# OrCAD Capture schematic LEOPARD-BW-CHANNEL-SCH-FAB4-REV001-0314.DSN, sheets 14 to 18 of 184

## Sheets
14 165_PVTT_GH_MOSFET: size A3; title: PVTT_GH_MOSFET
15 164_PVDDQ_GH_MOSFET: size C; title: PVDDQ_GH_MOSFET
16 163_PVDDQ_GH_Controller: size C; title: PVDDQ_GH_CONTROLLER
17 162_PVPP_EF_TPS53318: size A3; title: PVPP_EF_TPS53318
18 161_PVDDQ_EF_Decoupling: size A3; title: PVDDQ_EF_DECOUPLING

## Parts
sheet 161_PVDDQ_EF_Decoupling
PC545  SCD1U25V5KX-1GP  [C805H54]
PC546  SC1U25V6KX-2GP  [C1206H45]
PC547  SCD1U25V5KX-1GP  [C805H54]
PC548  SE470UF2VDM-GP  [CT7343H83]
PC549  SE470UF2VDM-GP  [CT7343H83]
PC550  SE470UF2VDM-GP  [CT7343H83]
PC551  SE470UF2VDM-GP  [CT7343H83]
PC552  SC47U4V5MX-2-GP  [C805H58]
PC553  SC47U4V5MX-2-GP  [C805H58]
PC554  SC47U4V5MX-2-GP  [C805H58]
PC555  SC47U4V5MX-2-GP  [C805H58]
PC556  SC22U6D3V5MX-5-GP  [C805H56]
PC557  SC22U6D3V5MX-5-GP  [C805H56]
PC558  SC22U6D3V5MX-5-GP  [C805H56]
PC559  SC22U6D3V5MX-5-GP  [C805H56]
PC560  SC22U6D3V5MX-5-GP  [C805H56]
PC561  SC22U6D3V5MX-5-GP  [C805H56]
PC562  SC22U6D3V5MX-5-GP  [C805H56]
PC563  SC22U6D3V5MX-5-GP  [C805H56]
PC564  SC22U6D3V5MX-5-GP  [C805H56]
PC565  SC22U6D3V5MX-5-GP  [C805H56]
PC566  SC22U6D3V5MX-5-GP  [C805H56]
PC567  SC22U6D3V5MX-5-GP  [C805H56]
PC568  SC22U6D3V5MX-5-GP  [C805H56]
PC569  SC22U6D3V5MX-5-GP  [C805H56]
PC570  SC22U6D3V5MX-5-GP  [C805H56]
PC571  SC22U6D3V5MX-5-GP  [C805H56]
PC572  SC22U6D3V5MX-5-GP  [C805H56]
PC573  SC22U6D3V5MX-5-GP  [C805H56]
PC574  SC22U6D3V5MX-5-GP  [C805H56]
PC575  SC22U6D3V5MX-5-GP  [C805H56]
PC576  SC22U6D3V5MX-5-GP  [C805H56]
PC577  SC22U6D3V5MX-5-GP  [C805H56]
PC578  SC22U6D3V5MX-5-GP  [C805H56]
PC579  SC22U6D3V5MX-5-GP  [C805H56]
PC580  SC22U6D3V5MX-5-GP  [C805H56]
PC581  SC22U6D3V5MX-5-GP  [C805H56]
PC582  SC22U6D3V5MX-5-GP  [C805H56]
PC583  SC22U6D3V5MX-5-GP  [C805H56]
PC584  SC22U6D3V5MX-5-GP  [C805H56]
PC585  SC22U6D3V5MX-5-GP  [C805H56]
PC586  SC22U6D3V5MX-5-GP  [C805H56]
PC587  SC22U6D3V5MX-5-GP  [C805H56]
PC588  SC22U6D3V5MX-5-GP  [C805H56]
PC589  SC22U6D3V5MX-5-GP  [C805H56]
PC590  SC22U6D3V5MX-5-GP  [C805H56]
PC591  SC22U6D3V5MX-5-GP  [C805H56]
PC592  SC22U6D3V5MX-5-GP  [C805H56]
PC593  SC22U6D3V5MX-5-GP  [C805H56]
PC594  SC22U6D3V5MX-5-GP  [C805H56]
PC595  SC22U6D3V5MX-5-GP  [C805H56]
PC857  SC22U6D3V5MX-5-GP  [C805H56]
PC858  SC22U6D3V5MX-5-GP  [C805H56]
PC859  SC22U6D3V5MX-5-GP  [C805H56]
PC860  SC22U6D3V5MX-5-GP  [C805H56]
PC861  SC22U6D3V5MX-5-GP  [C805H56]
PC862  SC22U6D3V5MX-5-GP  [C805H56]
PC863  SC22U6D3V5MX-5-GP  [C805H56]
PC864  SC22U6D3V5MX-5-GP  [C805H56]
PC1000  SC22U6D3V5MX-5-GP  [C805H56]
PC1001  SC22U6D3V5MX-5-GP  [C805H56]
PC1002  SC22U6D3V5MX-5-GP  [C805H56]
PL44  IND-65NH-GP  [L4038-1412H158]
PR329  33R3F-L-GP  [R603H22]
PR330  0R2F-L-GP  [R402H16]
PR331  0R2F-L-GP  [R402H16]
PTC7  E270U16VM-28-GP  [ECAP-100D6D3H363]
sheet 162_PVPP_EF_TPS53318
PC596  SC10U16V5KX-1-GP  [C805H54]
PC597  SC10U16V5KX-1-GP  [C805H54]
PC598  SC10U16V5KX-1-GP  [C805H54]
PC599  SC10U16V5KX-1-GP  [C805H54]
PC600  SCD1U16V3KX-3GP  [C603H36]
PC601  SC4D7U25V5KX-1-GP  [C805H58]
PC602  SCD1U50V3KX-GP  [C603H36]
PC603  SC2K2P50V3KX-GP  [C603]
PC604  SC1U10V2KX-4-GP  [C402H22]
PC605  SCD1U16V2KX-3GP  [C402H22]
PC606  SC1KP50V2KX-1GP  [C402H22]
PC607  SCD1U16V3KX-3GP  [C603H36]
PC608  SC22U6D3V5MX-5-GP  [C805H56]
PC609  SC47U4V5MX-2-GP  [C805H58]
PC610  SC47U4V5MX-2-GP  [C805H58]
PC611  SC47U4V5MX-2-GP  [C805H58]
PC612  SC47U4V5MX-2-GP  [C805H58]
PC613  SC47U4V5MX-2-GP  [C805H58]
PC614  SC47U4V5MX-2-GP  [C805H58]
PC1043  SC1U10V2KX-4-GP  [C402H22]
PD24  BZT52-C3V3S-GP  [SOD323AKH38]
PL29  BLM21PG220SN1DGP  [L20125H42]
PL30  IND-2D2UH-242-GP  [L7165-1732H119]
PR332  2D2R3-1-U-GP  [R603H22]
PR333  3D01R5F-GP  [R805H24]
PR335  0R2J-2-GP  [R402H16]
PR336  3K9R2F-GP  [R402H16]
PR337  10R3F-GP  [R603H22]
PR338  100KR2F-L1-GP  [R402H16]
PR339  3D01R5F-GP  [R805H24]
PR340  100KR2F-L1-GP  [R402H16]
PR341  100KR2F-L1-GP  [R402H16]
PR342  866KR2F-GP  [R402H16]
PR343  619KR2F-GP  [R402H16]
PR344  31K6R2F-GP  [R402H16]
PR345  10KR2F-2-GP  [R402H16]
PR346  0R3J-0-U-GP  [R603H22]
PR645  10KR2F-2-GP  [R402H16]
PR802  0R2J-2-GP  [R402H16]
PU30  TPS53318DQPR-GP  [DFN22G6050-G6133H60]
sheet 163_PVDDQ_GH_Controller
PC1469  SC220P50V2JN-3GP  [C402H22]
PC1487  SC1KP50V2KX-1GP  [C402H22]
PC1488  SC1U10V2KX-4-GP  [C402H22]
PC1489  SCD1U16V2KX-3GP  [C402H22]
PC1490  SC1U10V2KX-4-GP  [C402H22]
PC1491  SCD1U16V2KX-3GP  [C402H22]
PC1495  SC220P50V2KX-3GP  [C402H22]
PC1496  SCD47U25V3KX-3-GP  [C603H36]
PC1497  SC10U4V3MX-3-GP  [C603H40]
PC1498  SCD1U16V2KX-3GP  [C402H22]
PC1499  SC220P50V2KX-3GP  [C402H22]
PC1500  SC220P50V2JN-3GP  [C402H22]
PC1623  SC220P50V2JN-3GP  [C402H22]
PC7337  SCD47U6D3V2KX-1-GP  [C402H22]
PC7338  SCD47U6D3V2KX-1-GP  [C402H22]
PQ14  NST3906F3T5G-GP-U  [SOT-1123CBE1006-1H16]
PR1941  0R2J-2-GP  [R402H16]
PR2122  19K1R2F-GP  [R402H16]
PR2123  1KR2F-3-GP  [R402H16]
PR2124  0R2J-2-GP  [R402H16]
PR2128  1KR2F-3-GP  [R402H16]
PR2130  1KR2F-3-GP  [R402H16]
PR2131  0R2J-2-GP  [R402H16]
PR2132  0R2J-2-GP  [R402H16]
PR2133  10R3F-GP  [R603H22]
PR2135  0R2J-2-GP  [R402H16]
PR2136  0R0402-PAD-1-GP  [0R0402-PAD]
PR2139  16KR2F-GP  [R402H16]
PR2140  3K16R2F-GP  [R402H16]
PR2141  549R2F-GP  [R402H16]
PR2142  8K06R2F-GP  [R402H16]
PR2143  10R3F-GP  [R603H22]
PR2144  100R2F-L1-GP-U  [R402H14]
PR2145  0R2J-2-GP  [R402H16]
PR2146  100R2F-L1-GP-U  [R402H14]
PR2147  49D9R2F-GP  [R402H16]
PR2148  0R0402-PAD-1-GP  [0R0402-PAD]
PR2149  0R2J-2-GP  [R402H16]
PR2150  0R2J-2-GP  [R402H16]
PR2151  150R2F-1-GP  [R402H16]
PTP6  TP20B24R10-B-GP  [TP20B24R10-B]
PU31  PX3244HDM-1-GP  [QFN40J5-G3D75H36]
sheet 164_PVDDQ_GH_MOSFET
PC1566  SCD47U25V3KX-3-GP  [C603H36]
PC1567  SC10U16V5KX-1-GP  [C805H54]
PC1568  SC10U16V5KX-1-GP  [C805H54]
PC1569  SC10U16V5KX-1-GP  [C805H54]
PC1570  SCD1U16V2KX-3GP  [C402H22]
PC1571  SC1U25V3KX-GP  [C603H36]
PC1572  SCD1U16V2KX-3GP  [C402H22]
PC1573  SC1U10V2KX-4-GP  [C402H22]
PC1574  SCD22U16V2KX-GP  [C402H22]
PC1575  SC1U10V2KX-4-GP  [C402H22]
PC1576  SCD47U25V3KX-3-GP  [C603H36]
PC1577  SC10U16V5KX-1-GP  [C805H54]
PC1578  SC10U16V5KX-1-GP  [C805H54]
PC1579  SCD1U16V2KX-3GP  [C402H22]
PC1580  SC10U16V5KX-1-GP  [C805H54]
PC1581  SC1U25V3KX-GP  [C603H36]
PC1582  SCD1U16V2KX-3GP  [C402H22]
PC1583  SC1U10V2KX-4-GP  [C402H22]
PC1584  SCD22U16V2KX-GP  [C402H22]
PC1585  SC1U10V2KX-4-GP  [C402H22]
PG75  COPPER-CLOSE-GP-U  [CON2C-U]
PG76  COPPER-CLOSE-GP-U  [CON2C-U]
PG77  COPPER-CLOSE-GP-U  [CON2C-U]
PG78  COPPER-CLOSE-GP-U  [CON2C-U]
PL89  IND-150NH-15-GP  [L102078-254224H296]
PL96  IND-150NH-15-GP  [L102078-254224H296]
PR40  0R2J-2-GP  [R402H16]
PR41  0R2J-2-GP  [R402H16]
PR58  0R2J-2-GP  [R402H16]
PR59  0R2J-2-GP  [R402H16]
PR2217  1R2F-GP  [R402H16]
PR2254  1R2F-GP  [R402H16]
PR2255  10KR2F-2-GP  [R402H16]
PR2256  10KR2F-2-GP  [R402H16]
PR2275  0R3J-6-GP  [R603H22]
PR2277  0R3J-6-GP  [R603H22]
PR6655  562R2F-GP  [R402H16]
PR6656  562R2F-GP  [R402H16]
PR6669  562R2F-GP  [R402H16]
PR6670  562R2F-GP  [R402H16]
PTP35  TPAD24  [TPAD24]
PTP36  TPAD24  [TPAD24]
PTP49  TPAD24  [TPAD24]
PTP50  TPAD24  [TPAD24]
PU192  TDA21232-GP  [QFN31G5-G4P-7H38]
PU199  TDA21232-GP  [QFN31G5-G4P-7H38]
sheet 165_PVTT_GH_MOSFET
PC648  SC1U10V2KX-4-GP  [C402H22]
PC649  SCD22U16V2KX-GP  [C402H22]
PC651  SCD22U16V2KX-GP  [C402H22]
PC653  SC1U25V3KX-GP  [C603H36]
PC656  SC10U16V5KX-1-GP  [C805H54]
PC657  SC10U16V5KX-1-GP  [C805H54]
PC658  SCD47U25V3KX-3-GP  [C603H36]
PC659  SC220P50V2JN-3GP  [C402H22]
PC660  SC47U4V5MX-2-GP  [C805H58]
PC661  SC47U4V5MX-2-GP  [C805H58]
PC662  SC22U6D3V5MX-5-GP  [C805H56]
PC663  SC22U6D3V5MX-5-GP  [C805H56]
PC664  SC22U6D3V5MX-5-GP  [C805H56]
PC665  SC22U6D3V5MX-5-GP  [C805H56]
PC666  SC22U6D3V5MX-5-GP  [C805H56]
PC667  SC22U6D3V5MX-5-GP  [C805H56]
PC668  SC22U6D3V5MX-5-GP  [C805H56]
PC669  SC22U6D3V5MX-5-GP  [C805H56]
PC670  SC22U6D3V5MX-5-GP  [C805H56]
PC671  SC22U6D3V5MX-5-GP  [C805H56]
PC672  SC22U6D3V5MX-5-GP  [C805H56]
PC673  SC22U6D3V5MX-5-GP  [C805H56]
PC674  SE470UF2VDM-GP  [CT7343H83]
PG43  COPPER-CLOSE-GP-U  [CON2C-U]
PG44  COPPER-CLOSE-GP-U  [CON2C-U]
PL33  IND-1UH-101-GP  [L6868-3612H166]
PQ10  NST3906F3T5G-GP-U  [SOT-1123CBE1006-1H16]
PR392  2D2R2F-GP  [R402H16]
PR394  10KR2F-2-GP  [R402H16]
PR395  93K1R2F-L-GP  [R402H16]
PR398  562R2F-GP  [R402H16]
PR399  562R2F-GP  [R402H16]
PR400  0R2F-L-GP  [R402H16]
PR401  0R2F-L-GP  [R402H16]
PR402  120R3F-L-GP  [R603H22]
PR858  0R3J-0-U-GP  [R603H22]
PR859  0R3J-0-U-GP  [R603H22]
PU34  PX3517-GP  [DFN10G3-G2619H36]
PU35  AON7934-GP  [MLP8F3-G2P-1H32]

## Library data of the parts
PC545 PC547 = SCD1U25V5KX-1GP: CHIP CAP0.1U25V K0805 X7R(ROHS; GREENDFACTOR: R2_SA;HF_SA;G_SA;; Package Type: SMD-BCG; Part Number: 78.10422.21L; SPEC: http://wpqssvr.wistron.com.tw:7001/wpqs/servlet/COM.qpart.Attachment?PartNumber=78.10422.21L
PC546 = SC1U25V6KX-2GP: CHIP CAP C 1U 25V K1206 X7R; GREENDFACTOR: R2_SA;HF_SA;G_SA;; Package Type: SMD-BCG1; Part Number: 78.10522.22L; SPEC: http://wpqssvr.wistron.com.tw:7001/wpqs/servlet/COM.qpart.Attachment?PartNumber=78.10522.22L
PC548-PC551 PC674 = SE470UF2VDM-GP: CHIP CAP 470UF 2V EEFSX0D471X; GREENDFACTOR: R_SA;; Module: VR_DDR_P1V5_VDDQ; Package Type: SMD-TCG1; Part Number: 79.47719.2BL; Part Type: SMD-TCG1; Part_Function: Cout_bulk; Part_Spec: 470uF/2V/6mohm; Part_Type: Solid_al_cap; SPEC: http://wpqssvr.wistron.com.tw:7001/wpqs/servlet/COM.qpart.Attachment?PartNumber=79.47719.2BL; VENDOR_PN: EEFSX0D471XE
PC552-PC555 PC609-PC614 PC660 PC661 = SC47U4V5MX-2-GP: CHIP CAP C 47U 4V M0805 X6S; GREENDFACTOR: R2_SA;HF_SA;G_SA;; Package Type: SMD-BCG3; Part Number: 78.4761T.81L; SPEC: http://wpqssvr.wistron.com.tw:7001/wpqs/servlet/COM.qpart.Attachment?PartNumber=78.4761T.81L
PC556-PC595 PC608 PC662-PC673 PC857-PC864 = SC22U6D3V5MX-5-GP: CHIP CAP C 22U 6.3V M0805 X6S; GREENDFACTOR: R2_SA;HF_SA;G_SA;; Package Type: SMD-BCG2; Part Number: 78.22610.81L; SPEC: http://wpqssvr.wistron.com.tw:7001/wpqs/servlet/COM.qpart.Attachment?PartNumber=78.22610.81L
PC1000-PC1002 = SC22U6D3V5MX-5-GP: CHIP CAP C 22U 6.3V M0805 X6S; GREENDFACTOR: R2_SA;HF_SA;G_SA;; Package Type: SMD-BCG2; Part Number: 78.22610.81L; SPEC: http://wpqssvr.wistron.com.tw:7001/wpqs/servlet/COM.qpart.Attachment?PartNumber=78.22610.81L; Size: 0805; Type: X6S
PL44 = IND-65NH-GP: CHIP IND 65NH FP0404R1-R065-R; GREENDFACTOR: R2_SA;; Part Number: 68.650CN.101; Part Type: DISCRET-G6; SPEC: http://wpqssvr.wistron.com.tw:7001/wpqs/servlet/COM.qpart.Attachment?PartNumber=68.650CN.101
PR329 = 33R3F-L-GP: CHIP RES 33 F 1/10W 0603; GREENDFACTOR: R2_SA;HF_SA;G_SA;; Package Type: SMD-RG; Part Number: 64.33R05.55L; SPEC: http://wpqssvr.wistron.com.tw:7001/wpqs/servlet/COM.qpart.Attachment?PartNumber=64.33R05.55L
PR330 PR331 PR400 PR401 = 0R2F-L-GP: CHIP RES 0 F 0402 RK73Z1ETTP KOA; GREENDFACTOR: R2_SA;; Package Type: SMD-RG5; Part Number: 64.R0005.L0L; SPEC: http://wpqssvr.wistron.com.tw:7001/wpqs/servlet/COM.qpart.Attachment?PartNumber=64.R0005.L0L
PTC7 = E270U16VM-28-GP: CAP EL 270U 16V RT2.5 6.3*8 SOLID CAP; GREENDFACTOR: R2_SA;HF_SA;; Part Number: 09.2771D.E4L; Part Spec: 270uF/16V/10mohm/5A; Part Type: DIP-TCG4; SPEC: http://wpqssvr.wistron.com.tw:7001/wpqs/servlet/COM.qpart.Attachment?PartNumber=09.2771D.E4L
PC596-PC599 PC656 PC657 PC1567-PC1569 PC1577 PC1578 PC1580 = SC10U16V5KX-1-GP: CHIP CAP C 10U 16V K0805 X6S; GREENDFACTOR: R2_SA;; Package Type: SMD-BCG5; Part Number: 78.10621.81L; SPEC: http://wpqssvr.wistron.com.tw:7001/wpqs/servlet/COM.qpart.Attachment?PartNumber=78.10621.81L
PC600 PC607 = SCD1U16V3KX-3GP: CHIP CAP 0.1U16V K0603 X7R(ROH; GREENDFACTOR: R2_SA;R_SA;HF_SA;G_SA;; Module: VR_SYSTEM_P1V8; Package Type: SMD-BCG; Part Number: 78.10421.2BL; SPEC: http://wpqssvr.wistron.com.tw:7001/wpqs/servlet/COM.qpart.Attachment?PartNumber=78.10421.2BL; Size: 0603; Type: X7R
PC601 = SC4D7U25V5KX-1-GP: CHIP CAP C 4.7U 25V K0805 X7R; GREENDFACTOR: R2_SA;HF_SA;G_SA;; Package Type: SMD-BCG4; Part Number: 078.47522.0211; SPEC: http://wpqssvr.wistron.com.tw:7001/wpqs/servlet/COM.qpart.Attachment?PartNumber=078.47522.0211
PC602 = SCD1U50V3KX-GP: CHIP CAP C 0.1U 50V K0603 X7R; GREENDFACTOR: R2_SA;HF_SA;G_SA;; Level: SMD; MAIN_SOURCE: M; Package Type: RCL_GP; Part Number: 78.10424.2BL; Part Type: RCL_GP; SPEC: http://wpqssvr.wistron.com.tw:7001/wpqs/servlet/COM.qpart.Attachment?PartNumber=78.10424.2BL; Status: POP
PC603 = SC2K2P50V3KX-GP: CHIP CAP C 2200P 50V K0603 X7R; GREENDFACTOR: R2_SA;HF_SA;G_SA;; Level: SMD; POP?: NOPOP; Package Type: SMD-BCG6; Part Number: 78.22224.2BL; Part Type: SMD-BCG6; SPEC: http://wpqssvr.wistron.com.tw:7001/wpqs/servlet/COM.qpart.Attachment?PartNumber=78.22224.2BL; Status: POP
PC604 PC648 PC1488 PC1490 PC1573 PC1575 PC1583 PC1585 = SC1U10V2KX-4-GP: CHIP CAP C 1U 10V K 0402 X6S; GREENDFACTOR: R2_SA;HF_SA;; Package Type: SMD-BCG6; Part Number: 78.10523.8FL; SPEC: http://wpqssvr.wistron.com.tw:7001/wpqs/servlet/COM.qpart.Attachment?PartNumber=78.10523.8FL
PC605 PC1498 = SCD1U16V2KX-3GP: CHIP CAP C 0.1U 16V K0402 X7R; CATEGORIES: CAP_1.xV; GREENDFACTOR: R2_SA;HF_SA;G_SA;; MAIN_SOURCE: M; Part Number: 78.10421.2FL; Part Type: SMD-BCG; SPEC: http://wpqssvr.wistron.com.tw:7001/wpqs/servlet/COM.qpart.Attachment?PartNumber=78.10421.2FL
PC606 = SC1KP50V2KX-1GP: CHIP CAP 1000P50V K0402 X7R(RO; GREENDFACTOR: R2_SA;HF_SA;G_SA;; Level: SMD; MAIN_SOURCE: M; Package Type: SMD-BCG; Part Number: 78.10224.2FL; Part Type: SMD-BCG; SPEC: http://wpqssvr.wistron.com.tw:7001/wpqs/servlet/COM.qpart.Attachment?PartNumber=78.10224.2FL; Status: POP
PC1043 = SC1U10V2KX-4-GP: CHIP CAP C 1U 10V K 0402 X6S; GREENDFACTOR: R2_SA;HF_SA;; POP?: NOPOP; Package Type: SMD-BCG6; Part Number: 78.10523.8FL; SPEC: http://wpqssvr.wistron.com.tw:7001/wpqs/servlet/COM.qpart.Attachment?PartNumber=78.10523.8FL
PD24 = BZT52-C3V3S-GP: DIODE ZEN BZT52-C3V3S 3.3V SOD-323; GREENDFACTOR: R2_SA;; Part Number: 83.3R303.G3F; Part Type: DISCRET-G4; SPEC: http://wpqssvr.wistron.com.tw:7001/wpqs/servlet/COM.qpart.Attachment?PartNumber=83.3R303.G3F
PL29 = BLM21PG220SN1DGP: CHIP BEAD BLM21PG220SN1D (LF); GREENDFACTOR: R2_SA;HF_SA;; Level: SMD; Package Type: DISCRET-G; Part Number: 68.00084.831; Part Type: DISCRET-G; SPEC: http://wpqssvr.wistron.com.tw:7001/wpqs/servlet/COM.qpart.Attachment?PartNumber=68.00084.831; Status: POP
PL30 = IND-2D2UH-242-GP: CHIP IND 2.2UH M SPM6530T-2R2M; GREENDFACTOR: R2_SA;HF_SA;; Package Type: DISCRET-G6; Part Number: 68.2R21E.10X; SPEC: http://wpqssvr.wistron.com.tw:7001/wpqs/servlet/COM.qpart.Attachment?PartNumber=68.2R21E.10X
PR332 = 2D2R3-1-U-GP: CHIP RES 2.2 F 1/10W 0603(ROHS; GREENDFACTOR: R2_SA;HF_SA;G_SA;; Package Type: RCL_GP; Part Number: 64.2R205.55L; SPEC: http://wpqssvr.wistron.com.tw:7001/wpqs/servlet/COM.qpart.Attachment?PartNumber=64.2R205.55L
PR333 = 3D01R5F-GP: CHIP RES 3.01 F 1/8W 0805; GREENDFACTOR: R2_SA;HF_SA;G_SA;; Level: SMD; Package Type: SMD-RG5; Part Number: 64.3R015.16L; Part Type: SMD-RG5; SPEC: http://wpqssvr.wistron.com.tw:7001/wpqs/servlet/COM.qpart.Attachment?PartNumber=64.3R015.16L; Status: POP
PR335 PR802 = 0R2J-2-GP: CHIP RES 0 J 1/16W 0402; GREENDFACTOR: R2_SA;HF_SA;G_SA;; Level: SMD; Package Type: SMD-RG; Part Number: 63.R0034.1DL; Part Type: SMD-RG; ROOM: VR_CHIPSET; SPEC: http://wpqssvr.wistron.com.tw:7001/wpqs/servlet/COM.qpart.Attachment?PartNumber=63.R0034.1DL; Status: POP
PR336 = 3K9R2F-GP: CHIP RES 3.9K F 1/16W 0402; GREENDFACTOR: R2_SA;HF_SA;G_SA;; Package Type: RCL_GP; Part Number: 64.39015.6DL; SPEC: http://wpqssvr.wistron.com.tw:7001/wpqs/servlet/COM.qpart.Attachment?PartNumber=64.39015.6DL
PR337 PR2133 PR2143 = 10R3F-GP: CHIP RES 10 F 1/10W 0603; GREENDFACTOR: R2_SA;HF_SA;G_SA;; Level: SMD; Package Type: RCL_GP; Part Number: 64.10R05.55L; Part Type: RCL_GP; SPEC: http://wpqssvr.wistron.com.tw:7001/wpqs/servlet/COM.qpart.Attachment?PartNumber=64.10R05.55L; Status: POP
PR338 = 100KR2F-L1-GP: CHIP RES 100K F 1/16W 0402; GREENDFACTOR: R2_SA;HF_SA;G_SA;; Part Number: 64.10035.6DL; Part Type: SMD-RG; SPEC: http://wpqssvr.wistron.com.tw:7001/wpqs/servlet/COM.qpart.Attachment?PartNumber=64.10035.6DL
PR339 = 3D01R5F-GP: CHIP RES 3.01 F 1/8W 0805; GREENDFACTOR: R2_SA;HF_SA;G_SA;; Level: SMD; POP?: NOPOP; Package Type: SMD-RG5; Part Number: 64.3R015.16L; Part Type: SMD-RG5; SPEC: http://wpqssvr.wistron.com.tw:7001/wpqs/servlet/COM.qpart.Attachment?PartNumber=64.3R015.16L; Status: POP
PR340 = 100KR2F-L1-GP: CHIP RES 100K F 1/16W 0402; GREENDFACTOR: R2_SA;HF_SA;G_SA;; Level: SMD; POP?: NOPOP; Package Type: SMD-RG; Part Number: 64.10035.6DL; Part Type: SMD-RG; SPEC: http://wpqssvr.wistron.com.tw:7001/wpqs/servlet/COM.qpart.Attachment?PartNumber=64.10035.6DL; Status: NOPOP
PR341 = 100KR2F-L1-GP: CHIP RES 100K F 1/16W 0402; GREENDFACTOR: R2_SA;HF_SA;G_SA;; Package Type: SMD-RG; Part Number: 64.10035.6DL; SPEC: http://wpqssvr.wistron.com.tw:7001/wpqs/servlet/COM.qpart.Attachment?PartNumber=64.10035.6DL
PR342 = 866KR2F-GP: CHP RES 866K F 1/16W 0402; GREENDFACTOR: R2_SA;HF_SA;G_SA;; Level: SMD; POP?: NOPOP; Package Type: SMD-RG4; Part Number: 64.86635.6DL; Part Type: SMD-RG4; SPEC: http://wpqssvr.wistron.com.tw:7001/wpqs/servlet/COM.qpart.Attachment?PartNumber=64.86635.6DL; Status: POP
PR343 = 619KR2F-GP: CHIP RES 619K F 1/16W 0402; GREENDFACTOR: R2_SA;HF_SA;G_SA;; Level: SMD; POP?: NOPOP; Package Type: SMD-RG3; Part Number: 64.61935.6DL; Part Type: SMD-RG3; SPEC: http://wpqssvr.wistron.com.tw:7001/wpqs/servlet/COM.qpart.Attachment?PartNumber=64.61935.6DL; Status: NOPOP
PR344 = 31K6R2F-GP: CHIP RES 31.6K F 1/16W 0402; GREENDFACTOR: R2_SA;HF_SA;G_SA;; Package Type: RCL_GP; Part Number: 64.31625.6DL; SPEC: http://wpqssvr.wistron.com.tw:7001/wpqs/servlet/COM.qpart.Attachment?PartNumber=64.31625.6DL
PR345 = 10KR2F-2-GP: CHIP RES 10K F 1/16W 0402; GREENDFACTOR: R2_SA;HF_SA;G_SA;; Package Type: SMD-RG; Part Number: 64.10025.6DL; SPEC: http://wpqssvr.wistron.com.tw:7001/wpqs/servlet/COM.qpart.Attachment?PartNumber=64.10025.6DL
PR346 PR858 PR859 = 0R3J-0-U-GP: CHIP RES 0 J 1/10W 0603; GREENDFACTOR: R2_SA;HF_SA;G_SA;; Package Type: RCL_GP; Part Number: 63.00000.00L; SPEC: http://wpqssvr.wistron.com.tw:7001/wpqs/servlet/COM.qpart.Attachment?PartNumber=63.00000.00L
PR645 = 10KR2F-2-GP: CHIP RES 10K F 1/16W 0402; GREENDFACTOR: R2_SA;HF_SA;G_SA;; Level: SMD; Package Type: SMD-RG; Part Number: 64.10025.6DL; Part Type: SMD-RG; SPEC: http://wpqssvr.wistron.com.tw:7001/wpqs/servlet/COM.qpart.Attachment?PartNumber=64.10025.6DL
PU30 = TPS53318DQPR-GP: IC PWR CTRL TPS53318DQPR QFN 22P; GREENDFACTOR: R2_C;HF_C;; Package Type: DISCRET-G5; Part Number: 74.53318.073; SPEC: http://wpqssvr.wistron.com.tw:7001/wpqs/servlet/COM.qpart.Attachment?PartNumber=74.53318.073
PC659 PC1469 PC1500 PC1623 = SC220P50V2JN-3GP: CHIP CAP C 220P 50V J0402 NPO; GREENDFACTOR: R2_SA;HF_SA;G_SA;; Package Type: SMD-BCG; Part Number: 78.22134.1FL; SPEC: http://wpqssvr.wistron.com.tw:7001/wpqs/servlet/COM.qpart.Attachment?PartNumber=78.22134.1FL
PC1487 = SC1KP50V2KX-1GP: CHIP CAP 1000P50V K0402 X7R(RO; GREENDFACTOR: R2_SA;HF_SA;G_SA;; MAIN_SOURCE: M; Package Type: SMD-BCG; Part Number: 78.10224.2FL; SPEC: http://wpqssvr.wistron.com.tw:7001/wpqs/servlet/COM.qpart.Attachment?PartNumber=78.10224.2FL
PC1489 PC1491 = SCD1U16V2KX-3GP: CHIP CAP C 0.1U 16V K0402 X7R; GREENDFACTOR: R2_SA;HF_SA;G_SA;; MAIN_SOURCE: M; Package Type: SMD-BCG; Part Number: 78.10421.2FL; SPEC: http://wpqssvr.wistron.com.tw:7001/wpqs/servlet/COM.qpart.Attachment?PartNumber=78.10421.2FL
PC1495 PC1499 = SC220P50V2KX-3GP: CHIP CAP 220P50V K0402 X7R(ROH; GREENDFACTOR: R2_SA;HF_SA;G_SA;; MAIN_SOURCE: M; Package Type: SMD-BCG; Part Number: 78.22124.2FL; SPEC: http://wpqssvr.wistron.com.tw:7001/wpqs/servlet/COM.qpart.Attachment?PartNumber=78.22124.2FL
PC658 PC1496 PC1566 PC1576 = SCD47U25V3KX-3-GP: CHIP CAP C 0.47U 25V K0603 X7R; GREENDFACTOR: R2_SA;HF_SA;G_SA;; Part Number: 78.47422.2BL; Part Type: SMD-BCG5; SPEC: http://wpqssvr.wistron.com.tw:7001/wpqs/servlet/COM.qpart.Attachment?PartNumber=78.47422.2BL
PC1497 = SC10U4V3MX-3-GP: CHIP CAP C 10U 4V M0603 X6S; GREENDFACTOR: R2_C;; POP?: 078.1061T.08B1; Package Type: SMD-BCG6; Part Number: 78.1061T.8BL; SPEC: http://wpqssvr.wistron.com.tw:7001/wpqs/servlet/COM.qpart.Attachment?PartNumber=78.1061T.8BL
PC7337 PC7338 = SCD47U6D3V2KX-1-GP: CHIP CAP C 0.47U 6.3V K 0402 X6S; GREENDFACTOR: R2_SA;HF_SA;; Package Type: SMD-BCG3; Part Number: 78.47420.8FL; SPEC: http://wpqssvr.wistron.com.tw:7001/wpqs/servlet/COM.qpart.Attachment?PartNumber=78.47420.8FL
PQ10 PQ14 = NST3906F3T5G-GP-U: XTOR NST3906F3T5G PNP SOT-1123; GREENDFACTOR: R2_SA;HF_SA;; Package Type: DISCRET-G5; Part Number: 84.03906.01K; SPEC: http://wpqssvr.wistron.com.tw:7001/wpqs/servlet/COM.qpart.Attachment?PartNumber=84.03906.01K
PR1941 PR2145 = 0R2J-2-GP: CHIP RES 0 J 1/16W 0402; GREENDFACTOR: R2_SA;HF_SA;G_SA;; Part Number: 63.R0034.1DL; Part Type: SMD-RG; SPEC: http://wpqssvr.wistron.com.tw:7001/wpqs/servlet/COM.qpart.Attachment?PartNumber=63.R0034.1DL
PR2122 = 19K1R2F-GP: CHIP RES 19.1K F 1/16W 0402; GREENDFACTOR: R2_SA;HF_SA;G_SA;; Part Number: 64.19125.6DL; Part Type: RCL_GP; SPEC: http://wpqssvr.wistron.com.tw:7001/wpqs/servlet/COM.qpart.Attachment?PartNumber=64.19125.6DL
PR2123 PR2128 PR2130 = 1KR2F-3-GP: CHIP RES 1K F 1/16W 0402; GREENDFACTOR: R2_SA;HF_SA;G_SA;; Package Type: SMD-RG; Part Number: 64.10015.6DL; SPEC: http://wpqssvr.wistron.com.tw:7001/wpqs/servlet/COM.qpart.Attachment?PartNumber=64.10015.6DL
PR58 PR59 PR2124 PR2131 PR2132 PR2135 PR2149 PR2150 = 0R2J-2-GP: CHIP RES 0 J 1/16W 0402; GREENDFACTOR: R2_SA;HF_SA;G_SA;; Package Type: SMD-RG; Part Number: 63.R0034.1DL; SPEC: http://wpqssvr.wistron.com.tw:7001/wpqs/servlet/COM.qpart.Attachment?PartNumber=63.R0034.1DL
PR2136 PR2148 = 0R0402-PAD-1-GP: DUMMY PAD WITH WIRE RES 0 0402; GREENDFACTOR: R_C;; Module: VR_CPU_PVCC; Package Type: SMD-RG2; Part Number: ZZ.R0402.001; Part Type: SMD-RG2; Quotation: 8_1; SPEC: http://wpqssvr.wistron.com.tw:7001/wpqs/servlet/COM.qpart.Attachment?PartNumber=ZZ.R0402.001
PR2139 = 16KR2F-GP: CHIP RES 16K F 1/16W 0402; GREENDFACTOR: R2_SA;HF_SA;G_SA;; Module: VR_PVCORE_CPU; POP?: NOPOP; Package Type: SMD-RG; Part Number: 64.16025.6DL; Quotation: 8_1; SPEC: http://wpqssvr.wistron.com.tw:7001/wpqs/servlet/COM.qpart.Attachment?PartNumber=64.16025.6DL
PR2140 = 3K16R2F-GP: CHIP RES 3.16K F 1/16W 0402; GREENDFACTOR: R2_SA;HF_SA;G_SA;; Package Type: SMD-RG; Part Number: 64.31615.6DL; SPEC: http://wpqssvr.wistron.com.tw:7001/wpqs/servlet/COM.qpart.Attachment?PartNumber=64.31615.6DL
PR2141 = 549R2F-GP: CHIP RES 549 F 1/16W 0402; GREENDFACTOR: R2_SA;HF_SA;; Package Type: RCL_GP; Part Number: 64.54905.6DL; SPEC: http://wpqssvr.wistron.com.tw:7001/wpqs/servlet/COM.qpart.Attachment?PartNumber=64.54905.6DL
PR2142 = 8K06R2F-GP: CHIP RES 8.06K F 1/16W 0402; GREENDFACTOR: R2_SA;HF_SA;G_SA;; Package Type: RCL_GP; Part Number: 64.80615.6DL; SPEC: http://wpqssvr.wistron.com.tw:7001/wpqs/servlet/COM.qpart.Attachment?PartNumber=64.80615.6DL
PR2144 = 100R2F-L1-GP-U: CHIP RES 100 F 1/16W 0402; GREENDFACTOR: R2_SA;HF_SA;G_SA;; POP?: NOPOP; Package Type: SMD-RG; Part Number: 64.10005.6DL; SPEC: http://wpqssvr.wistron.com.tw:7001/wpqs/servlet/COM.qpart.Attachment?PartNumber=64.10005.6DL
PR2146 = 100R2F-L1-GP-U: CHIP RES 100 F 1/16W 0402; GREENDFACTOR: R2_SA;HF_SA;G_SA;; Package Type: SMD-RG; Part Number: 64.10005.6DL; SPEC: http://wpqssvr.wistron.com.tw:7001/wpqs/servlet/COM.qpart.Attachment?PartNumber=64.10005.6DL
PR2147 = 49D9R2F-GP: CHIP RES 49.9 F 1/16W 0402; GREENDFACTOR: R2_SA;HF_SA;G_SA;; Package Type: RCL_GP; Part Number: 64.49R95.6DL; SPEC: http://wpqssvr.wistron.com.tw:7001/wpqs/servlet/COM.qpart.Attachment?PartNumber=64.49R95.6DL
PR2151 = 150R2F-1-GP: CHIP RES 150 F 1/16W 0402; GREENDFACTOR: R2_SA;HF_SA;G_SA;; Package Type: SMD-RG; Part Number: 64.15005.6DL; SPEC: http://wpqssvr.wistron.com.tw:7001/wpqs/servlet/COM.qpart.Attachment?PartNumber=64.15005.6DL
PTP6 = TP20B24R10-B-GP_4: TEST VIA FOR DRILL 10MIL; GREENDFACTOR: R2_C;; Package Type: DISCRET-G5; Part Number: ZZ.0TPAD.211; SPEC: http://wpqssvr.wistron.com.tw:7001/wpqs/servlet/COM.qpart.Attachment?PartNumber=ZZ.0TPAD.211
PU31 = PX3244HDM-1-GP: IC CONVERTER PX3244HDM QFN 40P; GREENDFACTOR: R2_SA;; Part Number: 074.03244.0043; Part Type: ASIC-G5; SPEC: http://wpqssvr.wistron.com.tw:7001/wpqs/servlet/COM.qpart.Attachment?PartNumber=074.03244.0043
PC1570 PC1572 PC1579 PC1582 = SCD1U16V2KX-3GP: CHIP CAP C 0.1U 16V K0402 X7R; GREENDFACTOR: R2_SA;HF_SA;G_SA;; MAIN_SOURCE: M; Package Type: SMD-BCG; Part Number: 78.10421.2FL; SPEC: http://wpqssvr.wistron.com.tw:7001/wpqs/servlet/COM.qpart.Attachment?PartNumber=78.10421.2FL; Size: 0402; Type: X7R
PC653 PC1571 PC1581 = SC1U25V3KX-GP: CHIP CAP C 1U 25V K0603 X7R; GREENDFACTOR: R2_SA;HF_SA;G_SA;; Package Type: SMD-BCG; Part Number: 78.10522.2BL; SPEC: http://wpqssvr.wistron.com.tw:7001/wpqs/servlet/COM.qpart.Attachment?PartNumber=78.10522.2BL
PC649 PC651 PC1574 PC1584 = SCD22U16V2KX-GP: CHIP CAP C 0.22U 16V K0402 X7R; GREENDFACTOR: R2_SA;HF_SA;G_SA;; Package Type: SMD-BCG4; Part Number: 78.22421.2FL; SPEC: http://wpqssvr.wistron.com.tw:7001/wpqs/servlet/COM.qpart.Attachment?PartNumber=78.22421.2FL; Size: 0402; Type: X7R
PG43 PG44 PG75-PG78 = COPPER-CLOSE-GP-U: COPPER CLOSE; GREENDFACTOR: Regular;; Package Type: DISCRET-G9; Part Number: ZZ.CON2C.XXX; SPEC: http://wpqssvr.wistron.com.tw:7001/wpqs/servlet/COM.qpart.Attachment?PartNumber=ZZ.CON2C.XXX
PL89 PL96 = IND-150NH-15-GP: CHIP IND 150NH K FP1007R3-R15-R; GREENDFACTOR: R2_SA;; Part Number: 68.1512N.10E; Part Type: DISCRET-G9; SPEC: http://wpqssvr.wistron.com.tw:7001/wpqs/servlet/COM.qpart.Attachment?PartNumber=68.1512N.10E
PR40 PR41 = 0R2J-2-GP: CHIP RES 0 J 1/16W 0402; GREENDFACTOR: R2_SA;HF_SA;G_SA;; POP?: NOPOP; Package Type: SMD-RG; Part Number: 63.R0034.1DL; SPEC: http://wpqssvr.wistron.com.tw:7001/wpqs/servlet/COM.qpart.Attachment?PartNumber=63.R0034.1DL
PR2217 PR2254 = 1R2F-GP: CHIP RES 1 F 1/16W 0402; GREENDFACTOR: R2_SA;HF_SA;G_SA;; Package Type: SMD-RG; Part Number: 64.1R005.6DL; SPEC: http://wpqssvr.wistron.com.tw:7001/wpqs/servlet/COM.qpart.Attachment?PartNumber=64.1R005.6DL
PR394 PR2255 PR2256 = 10KR2F-2-GP: CHIP RES 10K F 1/16W 0402; GREENDFACTOR: R2_SA;HF_SA;G_SA;; POP?: NOPOP; Package Type: SMD-RG; Part Number: 64.10025.6DL; SPEC: http://wpqssvr.wistron.com.tw:7001/wpqs/servlet/COM.qpart.Attachment?PartNumber=64.10025.6DL
PR2275 PR2277 = 0R3J-6-GP: CHIP RES 0 J 1/10W 0603; GREENDFACTOR: R2_SA;HF_SA;G_SA;; Part Number: 63.R0033.15L; Part Type: SMD-RG1; SPEC: http://wpqssvr.wistron.com.tw:7001/wpqs/servlet/COM.qpart.Attachment?PartNumber=63.R0033.15L
PR398 PR399 PR6655 PR6656 PR6669 PR6670 = 562R2F-GP: CHIP RES 562 F 1/16W 0402; GREENDFACTOR: R2_SA;HF_SA;G_SA;; Package Type: SMD-RG; Part Number: 64.56205.6DL; SPEC: http://wpqssvr.wistron.com.tw:7001/wpqs/servlet/COM.qpart.Attachment?PartNumber=64.56205.6DL
PTP35 PTP36 PTP49 PTP50 = TPAD24: 24 MILS TEST PAD; GREENDFACTOR: Regular;; Package Type: DISCRET2; Part Number: ZZ.PAD24.001; SPEC: http://wpqssvr.wistron.com.tw:7001/wpqs/servlet/COM.qpart.Attachment?PartNumber=ZZ.PAD24.001
PU192 PU199 = TDA21232-GP: IC PWM TDA21232 IQFN 32P; GREENDFACTOR: R2_C;; Part Number: 074.21232.0073; Part Type: DISCRET-GB1; SPEC: http://wpqssvr.wistron.com.tw:7001/wpqs/servlet/COM.qpart.Attachment?PartNumber=074.21232.0073
PL33 = IND-1UH-101-GP: CHIP IND 1UH HCP0704-1R0-R; GREENDFACTOR: R2_SA;; Package Type: DISCRET-G6; Part Number: 68.1R090.10B; Part_Spec: 1.0uH/6.2mohm/17A; SPEC: http://wpqssvr.wistron.com.tw:7001/wpqs/servlet/COM.qpart.Attachment?PartNumber=68.1R090.10B; Vendor_PN: HCP0704-1R0-R
PR392 = 2D2R2F-GP: CHIP RES 2.2 F 1/16W 0402; GREENDFACTOR: R2_SA;HF_SA;G_SA;; Package Type: SMD-RG1; Part Number: 64.2R205.6DL; SPEC: http://wpqssvr.wistron.com.tw:7001/wpqs/servlet/COM.qpart.Attachment?PartNumber=64.2R205.6DL
PR395 = 93K1R2F-L-GP: CHIP RES 93.1K F 1/16W 0402; GREENDFACTOR: R2_SA;HF_SA;G_SA;; Package Type: SMD-RG; Part Number: 64.93125.6DL; SPEC: http://wpqssvr.wistron.com.tw:7001/wpqs/servlet/COM.qpart.Attachment?PartNumber=64.93125.6DL
PR402 = 120R3F-L-GP: CHIP RES 120 F 1/10W 0603; GREENDFACTOR: R2_SA;HF_SA;G_SA;; Package Type: SMD-RG; Part Number: 64.12005.55L; SPEC: http://wpqssvr.wistron.com.tw:7001/wpqs/servlet/COM.qpart.Attachment?PartNumber=64.12005.55L
PU34 = PX3517-GP: IC MOS DRV PX3517 DFN 10P; GREENDFACTOR: R2_C;; Module: VR_PVCORE_CPU; Package Type: DISCRET-G9; Part Number: 74.03517.0E3; Quotation: 8_1; SPEC: http://wpqssvr.wistron.com.tw:7001/wpqs/servlet/COM.qpart.Attachment?PartNumber=74.03517.0E3
PU35 = AON7934-GP: FET MOS AON7934 NC POWER DFN3X3A; GREENDFACTOR: R2_SA;HF_SA;; Part Number: 84.07934.037; Part Type: DISCRET-G7; SPEC: http://wpqssvr.wistron.com.tw:7001/wpqs/servlet/COM.qpart.Attachment?PartNumber=84.07934.037

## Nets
AGND_PVPP_EF: PR340.1 PR341.1 PR343.1 PR345.2 PR346.1 PR802.2
GND: PC545.2 PC546.2 PC547.2 PC548.2 PC549.2 PC550.2 PC551.2 PC552.2 PC553.2 PC554.2 PC555.2 PC556.2 PC557.2 PC558.2 PC559.2 PC560.2 PC561.2 PC562.2 PC563.2 PC564.2 PC565.2 PC566.2 PC567.2 PC568.2 PC569.2 PC570.2 PC571.2 PC572.2 PC573.2 PC574.2 PC575.2 PC576.2 PC577.2 PC578.2 PC579.2 PC580.2 PC581.2 PC582.2 PC583.2 PC584.2 PC585.2 PC586.2 PC587.2 PC588.2 PC589.2 PC590.2 PC591.2 PC592.2 PC593.2 PC594.2 PC595.2 PC596.2 PC597.2 PC598.2 PC599.2 PC600.2 PC601.2 PC604.1 PC607.2 PC608.2 PC609.2 PC610.2 PC611.2 PC612.2 PC613.2 PC614.2 PC648.2 PC649.2 PC651.2 PC653.2 PC656.2 PC657.2 PC659.1 PC660.2 PC661.2 PC662.2 PC663.2 PC664.2 PC665.2 PC666.2 PC667.2 PC668.2 PC669.2 PC670.2 PC671.2 PC672.2 PC673.2 PC674.2 PC857.2 PC858.2 PC859.2 PC860.2 PC861.2 PC862.2 PC863.2 PC864.2 PC1000.2 PC1001.2 PC1002.2 PC1043.1 PC1469.1 PC1487.2 PC1488.2 PC1489.2 PC1490.2 PC1491.2 PC1497.2 PC1498.2 PC1500.1 PC1567.2 PC1568.2 PC1569.2 PC1570.2 PC1571.2 PC1572.2 PC1573.1 PC1574.1 PC1575.1 PC1577.2 PC1578.2 PC1579.2 PC1580.2 PC1581.2 PC1582.2 PC1583.1 PC1584.1 PC1585.1 PC1623.1 PD24.A(ANODE) PQ10.B PQ10.C PQ14.B PQ14.C PR40.2 PR41.2 PR329.2 PR331.1 PR339.2 PR346.2 PR395.1 PR401.1 PR402.2 PR2123.2 PR2139.1 PR2140.1 PR2142.1 PTC7.2 PU30.23(GND) PU31.1(BVR_READY) PU31.22(ISEN3N) PU31.37(DNC#37) PU31.41(GND) PU34.5(GND) PU34.11(GND) PU35.5(S2#5) PU35.6(S2#6) PU35.7(S2#7) PU192.4(AGND) PU192.12(PGND) PU192.13(PGND) PU192.14(PGND) PU192.15(PGND) PU192.28(PGND) PU192.32(PGND) PU192.34(PGND) PU199.4(AGND) PU199.12(PGND) PU199.13(PGND) PU199.14(PGND) PU199.15(PGND) PU199.28(PGND) PU199.32(PGND) PU199.34(PGND) ; also on sheet 1 2 3 4 5 6 7 8 9 10 11 12 13 19 20 21 22 23 24 25 26 27 28 29 30 31 32 33 34 35 36 37 38 39 44 46 47 49 50 51 52 53 54 55 56 57 58 59 60 61 62 63 64 65 66 69 70 71 73 74 75 76 78 79 80 81 82 83 84 86 87 88 89 90 91 92 93 94 95 96 97 98 99 100 101 102 103 104 105 106 107 108 109 110 111 112 113 114 115 116 117 118 119 128 129 138 139 159 160 161 166 168 169 170 171 172 173 174 175 176 177 180 181 182 183 184
P3V3_STBY: PR58.2 PR59.2 PR645.1 PR2124.1 PR2128.1 PR2130.1 ; also on sheet 2 3 5 6 8 9 10 11 12 20 21 22 25 26 27 30 31 33 34 35 37 38 39 45 47 49 50 51 52 54 55 59 60 61 62 63 64 65 66 69 70 71 72 73 74 76 79 83 84 87 88 89 90 91 92 93 94 95 96 97 98 99 159 161 166 168 173 174 176 177 179 180 182 183 184
P5V_STBY: PC1574.2 PC1575.2 PC1584.2 PC1585.2 PR392.1 PR2217.1 PR2254.1 PU192.29(PVCC) PU199.29(PVCC) ; also on sheet 4 5 6 8 19 20 24 25 29 30 33 34 37 38 59 61 65 69 76 95
P12V_STBY: PC545.1 PC546.1 PL29.1 PL44.1 PR332.1 ; also on sheet 2 3 4 7 9 10 11 12 13 22 23 27 28 32 36 59 60 75 95 104 105 106 107 108 109 110 111 112 113 114 115 116 117 118 119
PVCCIO: PC1497.1 PC1498.1 PR2144.1 PR2146.1 PR2147.1 ; also on sheet 11 26 35 39 46 47 68 87 97 100 101 102 103 120 129 130 139 160 173 177 179 182
PVDDQ_EF: PC548.1 PC549.1 PC550.1 PC551.1 PC552.1 PC553.1 PC554.1 PC555.1 PC556.1 PC557.1 PC558.1 PC559.1 PC560.1 PC561.1 PC562.1 PC563.1 PC564.1 PC565.1 PC566.1 PC567.1 PC568.1 PC569.1 PC570.1 PC571.1 PC572.1 PC573.1 PC574.1 PC575.1 PC576.1 PC577.1 PC578.1 PC579.1 PC580.1 PC581.1 PC582.1 PC583.1 PC584.1 PC585.1 PC586.1 PC587.1 PC588.1 PC589.1 PC590.1 PC591.1 PC592.1 PC593.1 PC594.1 PC595.1 PC857.1 PC858.1 PC859.1 PC860.1 PC861.1 PC862.1 PC863.1 PC864.1 PC1000.1 PC1001.1 PC1002.1 PR329.1 PR330.1 ; also on sheet 20 45 97 108 109 110 111 120 129
PVDDQ_EF_VIN: PC547.1 PL44.2 PTC7.1 ; also on sheet 19 20 21
PVDDQ_EF_VSENN_R: PR331.2 ; also on sheet 21
PVDDQ_EF_VSENP_R: PR330.2 ; also on sheet 21
PVDDQ_GH: PG76.2 PG78.2 PL89.2(F) PL96.2(F) ; also on sheet 13 45 97 104 105 106 107 120 129
PVDDQ_GH_ALERT: PR2149.1 PU31.13(ALERT#)
PVDDQ_GH_BOOT1: PR2275.1 PU192.5(BOOT)
PVDDQ_GH_BOOT2: PR2277.1 PU199.5(BOOT)
PVDDQ_GH_EN: PR2131.2 PU31.8(VR_EN)
PVDDQ_GH_EN1: PR58.1 PU192.31(EN)
PVDDQ_GH_EN2: PR59.1 PU199.31(EN)
PVDDQ_GH_FAULT: PR2135.1 PU31.38(FAULT1)
PVDDQ_GH_GH1: PTP36.1 PU192.6(GH)
PVDDQ_GH_GH2: PTP50.1 PU199.6(GH)
PVDDQ_GH_GL1: PTP35.1 PU192.27(GL#27)
PVDDQ_GH_GL2: PTP49.1 PU199.27(GL#27)
PVDDQ_GH_IMON: PTP6.1 PU31.20(IMON/FAULT2)
PVDDQ_GH_ISEN1N: PC7337.2 PR6656.2 PU31.28(ISEN1N)
PVDDQ_GH_ISEN1P: PC7337.1 PG76.1 PU31.29(ISEN1P)
PVDDQ_GH_ISEN2N: PC7338.2 PR6670.2 PU31.25(ISEN2N)
PVDDQ_GH_ISEN2P: PC7338.1 PG78.1 PU31.26(ISEN2P)
PVDDQ_GH_PG: PR2130.2 PR2132.2 PU31.7(VR_READY)
PVDDQ_GH_PHASE1: PC1576.2 PU192.7(PHASE)
PVDDQ_GH_PHASE1_R: PC1576.1 PR2275.2
PVDDQ_GH_PHASE2: PC1566.2 PU199.7(PHASE)
PVDDQ_GH_PHASE2_R: PC1566.1 PR2277.2
PVDDQ_GH_PWM1: PU31.4(PWM1) PU192.1(PWM)
PVDDQ_GH_PWM2: PU31.5(PWM2) PU199.1(PWM)
PVDDQ_GH_SADDR_L: PR2140.2 PU31.24(SADDR_L)
PVDDQ_GH_SADDR_M: PR2139.2 PU31.21(SADDR_M)
PVDDQ_GH_SW#1: PG75.2 PL89.1(S) PU192.16(SW#16) PU192.17(SW#17) PU192.18(SW#18) PU192.19(SW#19) PU192.20(SW#20) PU192.21(SW#21) PU192.22(SW#22) PU192.23(SW#23) PU192.24(NC#24) PU192.25(NC#25) PU192.26(NC#26)
PVDDQ_GH_SW#1_N: PG75.1 PR6655.2
PVDDQ_GH_SW#1_R: PR6655.1 PR6656.1
PVDDQ_GH_SW#2: PG77.2 PL96.1(S) PU199.16(SW#16) PU199.17(SW#17) PU199.18(SW#18) PU199.19(SW#19) PU199.20(SW#20) PU199.21(SW#21) PU199.22(SW#22) PU199.23(SW#23) PU199.24(NC#24) PU199.25(NC#25) PU199.26(NC#26)
PVDDQ_GH_SW#2_N: PG77.1 PR6669.2
PVDDQ_GH_SW#2_R: PR6669.1 PR6670.1
PVDDQ_GH_TMON1: PR40.1 PU192.30(PHFLT#)
PVDDQ_GH_TMON2: PR41.1 PU199.30(PHFLT#)
PVDDQ_GH_TSEN: PC1623.2 PR1941.1 PU31.27(TSEN)
PVDDQ_GH_TSEN_R: PC1469.2 PQ14.E PR1941.2
PVDDQ_GH_VADDR: PR2142.2 PU31.17(VADDR)
PVDDQ_GH_VCC1: PC1583.2 PR2217.2 PR2256.2 PU192.3(VCC)
PVDDQ_GH_VCC2: PC1573.2 PR2254.2 PR2255.2 PU199.3(VCC)
PVDDQ_GH_VCLK: PR2151.1 PU31.11(VCLK)
PVDDQ_GH_VD15: PC1490.1 PC1491.1 PU31.40(VD15)
PVDDQ_GH_VDD: PC1488.1 PC1489.1 PR2124.2 PU31.31(VDD)
PVDDQ_GH_VDIO: PR2150.1 PU31.12(VDIO)
PVDDQ_GH_VIN: PC651.1 PC653.1 PC656.1 PC657.1 PC1567.1 PC1568.1 PC1569.1 PC1570.1 PC1571.1 PC1572.1 PC1577.1 PC1578.1 PC1579.1 PC1580.1 PC1581.1 PC1582.1 PR2122.2 PU35.2(D1#2) PU35.3(D1#3) PU35.4(D1#4) PU35.9(D1#9) PU192.8(VIN) PU192.9(VIN) PU192.10(VIN) PU192.11(VIN) PU192.33(VIN) PU199.8(VIN) PU199.9(VIN) PU199.10(VIN) PU199.11(VIN) PU199.33(VIN) ; also on sheet 13
PVDDQ_GH_VINSEN: PC1487.1 PR2122.1 PR2123.1 PU31.30(VINSEN)
PVDDQ_GH_VSENN: PC1495.2 PR2136.2 PU31.19(VSENN)
PVDDQ_GH_VSENN_R: PR2136.1 ; also on sheet 13
PVDDQ_GH_VSENP: PC1495.1 PR2133.1 PU31.18(VSENP)
PVDDQ_GH_VSENP_R: PR2133.2 ; also on sheet 13
PVDDQ_GH_ZCD#1: PR2256.1 PU192.2(NC#2)
PVDDQ_GH_ZCD#2: PR2255.1 PU199.2(NC#2)
FM_VPP_MEM_EFGH_EN: PR335.1 ; also on sheet 12 51
IRQ_PVDDQ_GH_VRHOT_LVT3_N: PR2128.2 PU31.39(VR_HOT#) ; also on sheet 177 181
PVPP_EF: PC605.1 PC607.1 PC608.1 PC609.1 PC610.1 PC611.1 PC612.1 PC613.1 PC614.1 PD24.K(CATHODE) PL30.2(F) PR337.1 ; also on sheet 108 109 110 111 160
PVPP_EF_EN: PC1043.2 PR335.2 PU30.2(EN)
PVPP_EF_LL: PC602.2 PC603.1 PL30.1(S) PR336.1 PU30.6(LL#6) PU30.7(LL#7) PU30.8(LL#8) PU30.9(LL#9) PU30.10(LL#10) PU30.11(LL#11)
PVPP_EF_LL_R: PC605.2 PC606.1 PR336.2
PVPP_EF_MODE: PR338.1 PR340.2 PU30.20(MODE)
PVPP_EF_PWRGD: PR338.2 PR645.2 PU30.3(PGOOD) ; also on sheet 21
PVPP_EF_RF: PR342.2 PR343.2 PU30.22(RF)
PVPP_EF_ROVP: PR802.1 PU30.5(ROVP)
PVPP_EF_SNB: PC603.2 PR339.1
PVPP_EF_TRIP: PR341.2 PU30.21(TRIP)
PVPP_EF_VBST: PR333.1 PU30.4(VBST)
PVPP_EF_VBST_RC: PC602.1 PR333.2
PVPP_EF_VDD: PC601.1 PR332.2 PU30.19(VDD)
PVPP_EF_VFB: PC606.2 PR344.1 PR345.1 PU30.1(VFB)
PVPP_EF_VFB_R: PR337.2 PR344.2
PVPP_EF_VIN: PC596.1 PC597.1 PC598.1 PC599.1 PC600.1 PL29.2 PU30.12(VIN) PU30.13(VIN) PU30.14(VIN) PU30.15(VIN) PU30.16(VIN) PU30.17(VIN)
PVPP_EF_VREG: PC604.2 PR342.1 PU30.18(VREG)
PVPP_GH_PWRGD: PR2131.1 ; also on sheet 12
PVTT_GH: PC660.1 PC661.1 PC662.1 PC663.1 PC664.1 PC665.1 PC666.1 PC667.1 PC668.1 PC669.1 PC670.1 PC671.1 PC672.1 PC673.1 PC674.1 PG44.2 PL33.2(S) PR400.1 PR402.1 ; also on sheet 104 105 106 107
PVTT_GH_BISEN_N: PR398.2 PR399.1
PVTT_GH_BISEN_N_R: PG43.1 PR398.1
PVTT_GH_BISENN: PC1496.2 PR399.2 PR2141.2 PU31.33(BISENN)
PVTT_GH_BISENP: PC1496.1 PG44.1 PR2141.1 PU31.34(BISENP)
PVTT_GH_BPWM: PU31.2(BPWM) PU34.4(PWM)
PVTT_GH_BST: PC658.1 PU34.2(BOOT)
PVTT_GH_BTSEN: PC1500.2 PR2145.2 PU31.32(BTSEN)
PVTT_GH_BTSEN_R: PC659.2 PQ10.E PR2145.1
PVTT_GH_BVSENN: PC1499.2 PR2148.2 PU31.35(BVSENN)
PVTT_GH_BVSENP: PC1499.1 PR2143.1 PU31.36(BVSENP)
PVTT_GH_LGATE: PR858.2 PU34.6(LGATE)
PVTT_GH_LGATE_R: PR858.1 PU35.8(G2)
PVTT_GH_PH: PC658.2 PG43.2 PL33.1(F) PR394.2 PU34.10(PHASE) PU35.10(S1/D2)
PVTT_GH_PVCC: PC648.1 PC649.1 PR392.2 PU34.7(VCC) PU34.9(PVCC)
PVTT_GH_RT: PR395.2 PU34.8(RT)
PVTT_GH_UGATE: PR394.1 PR859.2 PU34.1(UGATE)
PVTT_GH_UGATE_R: PR859.1 PU35.1(G1)
PVTT_GH_VSENN_R: PR401.2 PR2148.1
PVTT_GH_VSENP_R: PR400.2 PR2143.2
PWRGD_PVPP_PVDDQ_GH: PR2132.1 ; also on sheet 51
SMB_VR_STBY_LVC3_CLK: PU31.10(SCL) ; also on sheet 21 26 31 35 39 74 161
SMB_VR_STBY_LVC3_DATA: PU31.9(SDA) ; also on sheet 21 26 31 35 39 74 161
SVID_ALERT_CPU1_N: PR2144.2 PR2149.2 ; also on sheet 21 35 129
SVID_CLK_CPU1: PR2147.2 PR2151.2 ; also on sheet 21 35 129
SVID_DIO_CPU1: PR2146.2 PR2150.2 ; also on sheet 21 35 129
VR_FAIL_PVCC_CPU_N: PR2135.2 ; also on sheet 21 26 31 35 39 74

Not connected (* = marked no-connect by the designer): PU31 3(DR_EN)* 6(PWM3)* 14(RESET#)* 15(DNC#15)* 16(DNC#16)* 23(ISEN3P)*; PU34 3(THW#)*; PU192 35(GL#35)*; PU199 35(GL#35)*

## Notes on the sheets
sheet 14
- Power rail : PVTT_GH
  Controller : PX3244H+PX3517+BSZ0907
  TDC : 2A
  Max : 3.6A
  OCP : 6A
  Sinking/Souring : +/-1.14A
  Max Transient Sinking : -1.02A
  Max Transient Sourcing : +0.46A
  Slew rate : 4.67A
  Step Size : 1.48A
- FAB1 REV013 20150413
- Change to 63.00000.00L
- FAB1 REV008 20150326
- Differential Pair
- Place near PL33
- Differential Pair
- Place at the middle of the central DIM
- Routed As Differential Pair
- Place After Lout
- Memory Slot Capacitors
- Place Capcitors Under Output Inductors on Bottom Side
sheet 15
- PVDDQ_GH_MOSFET
- FP1007R3-R15-R
  150nH/0.29mohm/61A
  7.8*10.2*7.3 mm
- FP1007R3-R15-R
  150nH/0.29mohm/61A
  7.8*10.2*7.3 mm
sheet 16
- Power rail : PVDDQ_GH
  Controller : PX3244H
  Min current : 2.59A
  TDC : 36.93A
  Max : 37.87A
  Step Size : 35.28A
  Slew rate : 16.72 A/us
  OCP : 46A
  I2C address : 14
  SVID address : 04
  DDR Type : LR-DIMM
  Level : DDR4
  Process (nm Technology) : 2x
  Physical Rank : 4
  DRAM width : x4
  Speed (MHz) : 2400
  DRAM tech : 4Gb
  DPC (DIMM Per Channel) : 2
  Page : open
  Burst Length : 8
  # of CH/Skt used :4
  Refresh : 2x
  # Memory CHs/VR for VDD/VTT : 2
  # Memory CHs/VR for VPP : 2
- Routed As Differential Pair
- close Phase 1 between phase 2
- Routed As Differential Pair
- VDDQ Measurement point for Bode
- Routed As Differential Pair
- PVDDQ_GH I2C address:14
- Routed As Differential Pair
- Use Daisy Chian
- PDG P.252
- PVDDQ_GH SVID address:04
- Vtt Measurement point for Bode
- Routed As Differential Pair
- Routed As Differential Pair
sheet 17
- Power rail : PVPP_EF(2V5)
  Controller : TPS53318 (Fswitching=500KHz)
  TDC : 3.24A
  MAX : 6.6A
  OCP : 8.5A
- I_rated=6A
  DCR=20mohm
  Z=22ohm
- TDK SPM6530T-2R2M
  L=2.2uH, DCR=17.3 mohm,
- FCCM Mode
- SS=5.6ms
- OCP = 8.5A
- FS=500KHz
- Vout=0.6x(1+Ru/Rd)
sheet 18
- PVDDQ_EF Decoupling
- PVDDQ_EF LC Filter
- Place Capcitors Under Output Inductors on Bottom Side
- Place After Lout
- Place in CPU Socket Cavity
- Routed As Differential Pair
- Memory Slot Capacitors
